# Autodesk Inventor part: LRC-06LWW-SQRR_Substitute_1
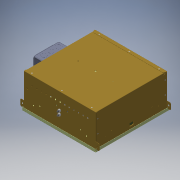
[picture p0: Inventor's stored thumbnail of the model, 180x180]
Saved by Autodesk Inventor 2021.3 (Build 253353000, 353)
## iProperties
Part Number: LRC-06LWW-SQRR_Substitute_1
Material: Generic
Document SubType Name: Modeling
Designer: JChurch
Manufacturer: Standard
Standards Organization: Custom
Density: 1 g/cm^3
Appearance: Smooth - Black
Author: JChurch
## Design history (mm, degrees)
derived "LRC-06LWW-SQRR.iam"
body "Solid9"
node "830376-00-00.iam:1::830376-PAN.ipt:1"
node "830376-00-00.iam:1::830376-FLANGE.ipt:1"
body "Solid10"
node "830376-00-00.iam:1::506010-00-38 SQUEEZED.ipt:1"
body "Solid11"
node "830376-00-00.iam:1::506010-00-38 SQUEEZED.ipt:2"
body "Solid12"
node "830376-00-00.iam:1::506010-00-38 SQUEEZED.ipt:3"
body "Solid13"
node "830376-00-00.iam:1::506010-00-38 SQUEEZED.ipt:4"
body "Solid14"
node "830376-00-00.iam:1::506010-00-38 SQUEEZED.ipt:5"
body "Solid15"
node "830376-00-00.iam:1::506010-00-38 SQUEEZED.ipt:6"
body "Solid16"
node "830376-00-00.iam:1::506010-00-38 SQUEEZED.ipt:7"
body "Solid17"
node "830376-00-00.iam:1::506010-00-38 SQUEEZED.ipt:8"
body "Solid18"
node "830376-00-00.iam:1::830376-FLANGE.ipt:2"
body "Solid19"
node "881088-00-00.iam:1::830140-00-00.ipt:1"
body "Solid20"
node "881088-00-00.iam:1::850014-00-00.iam:1::805044-00-00.ipt:1"
body "Solid21"
node "881088-00-00.iam:1::850014-00-00.iam:1::805174-00-00.ipt:1"
body "Solid22"
node "881088-00-00.iam:1::850014-00-00.iam:1::502055-00-00.ipt:1"
body "Solid23"
node "881088-00-00.iam:1::850014-00-00.iam:1::502055-00-00.ipt:2"
body "Solid24"
node "881088-00-00.iam:1::850014-00-00.iam:1::507032-00-00.ipt:1"
body "Solid25"
node "881088-00-00.iam:1::507000-00-00.ipt:1"
body "Solid26"
node "881088-00-00.iam:1::507000-00-00.ipt:2"
body "Solid27"
node "881088-00-00.iam:1::506002-00-00.ipt:1"
body "Solid28"
node "881088-00-00.iam:1::506002-00-00.ipt:2"
body "Solid29"
node "881088-00-00.iam:1::506002-00-00.ipt:3"
body "Solid30"
node "881088-00-00.iam:1::506002-00-00.ipt:4"
body "Solid31"
node "881088-00-00.iam:1::506002-00-00.ipt:5"
body "Solid32"
node "881088-00-00.iam:1::506002-00-00.ipt:6"
body "Solid33"
node "881088-00-00.iam:1::506002-00-00.ipt:7"
body "Solid34"
node "881088-00-00.iam:1::506002-00-00.ipt:8"
body "Solid35"
node "881088-00-00.iam:1::506002-00-00.ipt:9"
body "Solid36"
node "881088-00-00.iam:1::506002-00-00.ipt:10"
body "Solid37"
node "881088-00-00.iam:1::506002-00-00.ipt:11"
body "Solid38"
node "881088-00-00.iam:1::506002-00-00.ipt:12"
body "Solid39"
node "881088-00-00.iam:1::506002-00-00.ipt:13"
body "Solid40"
node "881088-00-00.iam:1::506002-00-00.ipt:14"
body "Solid41"
node "881088-00-00.iam:1::830392-01-00.iam:1::830392-00-00.ipt:1"
body "Solid42"
node "881088-00-00.iam:1::830392-01-00.iam:1::500027-00-00.ipt:1"
body "Solid43"
node "881088-00-00.iam:1::830392-01-00.iam:1::501030-00-00.ipt:1"
body "Solid44"
node "881088-00-00.iam:1::830392-01-00.iam:1::500027-00-00.ipt:2"
body "Solid45"
node "881088-00-00.iam:1::830392-01-00.iam:1::501030-00-00.ipt:2"
body "Solid46"
node "881088-00-00.iam:1::830392-01-00.iam:1::501030-00-00.ipt:3"
body "Solid47"
node "881088-00-00.iam:1::830392-01-00.iam:1::501030-00-00.ipt:4"
body "Solid48"
node "881088-00-00.iam:1::830392-01-00.iam:2::830392-00-00.ipt:1"
body "Solid49"
node "881088-00-00.iam:1::830392-01-00.iam:2::500027-00-00.ipt:1"
body "Solid50"
node "881088-00-00.iam:1::830392-01-00.iam:2::501030-00-00.ipt:1"
body "Solid51"
node "881088-00-00.iam:1::830392-01-00.iam:2::500027-00-00.ipt:2"
body "Solid52"
node "881088-00-00.iam:1::830392-01-00.iam:2::501030-00-00.ipt:2"
body "Solid53"
node "881088-00-00.iam:1::830392-01-00.iam:2::501030-00-00.ipt:3"
body "Solid54"
node "881088-00-00.iam:1::830392-01-00.iam:2::501030-00-00.ipt:4"
body "Solid55"
node "700466-25-XX (NEW).iam:1::700466-25-XX BRACKET-LEFT.ipt:1"
body "Solid56"
node "700466-25-XX (NEW).iam:1::700466-25-XX BRACKET-CENTER.ipt:1"
body "Solid57"
node "700466-25-XX (NEW).iam:1::700466-25-RF.ipt:1"
body "Solid58"
node "700466-25-XX (NEW).iam:1::700466-25-RF1.ipt:1"
body "Solid59"
node "700466-25-XX (NEW).iam:1::700466-25-RF2.ipt:1"
body "Solid60"
node "700466-25-XX (NEW).iam:1::700466-25-XX BRACKET-LEFT_MIR.ipt:"
body "Solid61"
node "700466-25-XX (NEW).iam:1::700466-25-RF2_MIR.ipt:1"
body "Solid62"
node "725267-00-00.ipt:1"
body "Solid63"
other parameters: "d15" = 61.595, "d16" = 9.525, "d17" = 9.525, "d35" = 5.08
